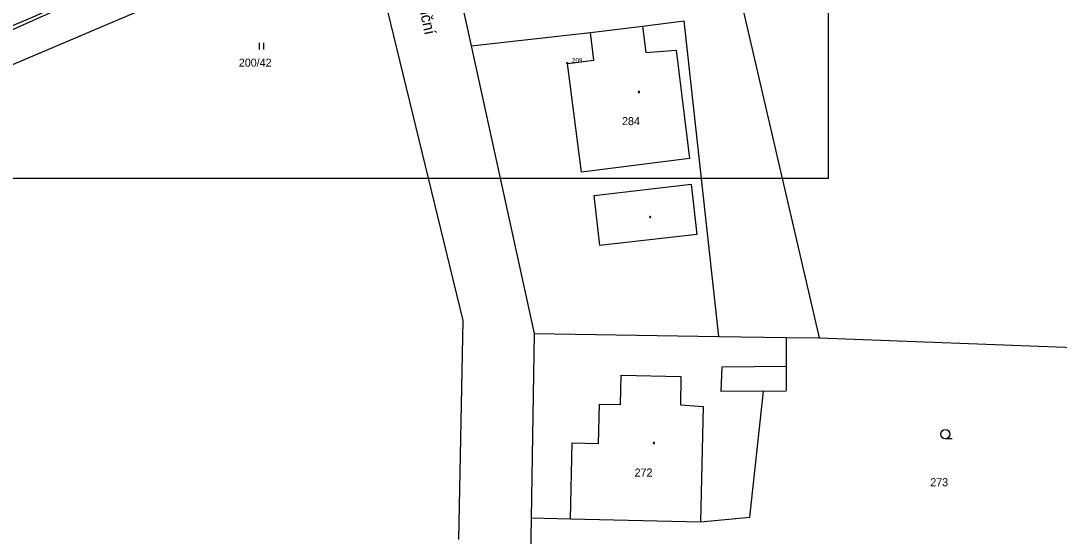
# Model space of a CAD drawing. Extents: x -454285 to -453563, y -1108687 to -1108249.
# Drawn here: x -454018.7 to -453927.9, y -1108561.2 to -1108516.1 of the extents above; entities that cross this region are included whole.
import ezdxf

# ---------------------------------------------------------------- set-up
doc = ezdxf.new("R2010")
doc.units = 0
for name, color, linetype in [('1', 7, 'Continuous'), ('14', 7, 'Continuous'), ('15', 7, 'Continuous'), ('16', 7, 'Continuous'), ('2', 7, 'Continuous'), ('23', 7, 'Continuous'), ('25', 7, 'Continuous'), ('38', 7, 'Continuous'), ('BODY_T1_2018', 7, 'Continuous'), ('CISLA_T1_2018', 7, 'Continuous'), ('okraj asf.komunikace', 7, 'Continuous'), ('rámy', 7, 'Continuous')]:
    doc.layers.add(name, color=color, linetype=linetype)

# ---------------------------------------------------------------- blocks, each defined once
blk = doc.blocks.new('Z402')
for start, end in [(0, 180), (180, 0)]:
    blk.add_arc((0, 0), 0.15, start, end)
blk = doc.blocks.new('Z3040')
blk.add_line((1.5, 0), (0, 0))
blk.add_circle((0, 1), 1)
blk = doc.blocks.new('Z3060')
for p, q in [((-0.5, 1.5), (-0.5, 0)), ((0.5, 1.5), (0.5, 0))]:
    blk.add_line(p, q)
blk = doc.blocks.new('POINT_DISPLAY')
for p, q in [((-0.1, 0), (0.1, 0)), ((0, -0.1), (0, 0.1))]:
    blk.add_line(p, q)
blk.add_circle((0, 0), 0.05)
blk = doc.blocks.new('t1_2018')
at = {"layer": 'BODY_T1_2018'}
blk.add_blockref('POINT_DISPLAY', (-453970.87, -1108519.81), dxfattribs=at)
at = {"layer": 'CISLA_T1_2018'}
blk.add_text('209', height=0.4, dxfattribs=at).set_placement((-453970.47, -1108519.75))

msp = doc.modelspace()

# ---------------------------------------------------------------- linework, layer by layer
at = {"layer": '1'}
for p, q in [((-453960.007, -1108495.681), (-453948.847, -1108543.851)), ((-453982.257, -1108504.751), (-453979.297, -1108518.271)), ((-453988.627, -1108506.811), (-454099.187, -1108553.971)), ((-453979.987, -1108542.331), (-453988.627, -1108506.811)), ((-453968.857, -1108517.121), (-453964.297, -1108516.551)), ((-453964.297, -1108516.551), (-453960.657, -1108516.091)), ((-453957.627, -1108543.721), (-453960.657, -1108516.091)), ((-453979.297, -1108518.271), (-453968.857, -1108517.121)), ((-453979.297, -1108518.271), (-453973.777, -1108543.471)), ((-453980.367, -1108561.481), (-453979.987, -1108542.331)), ((-453973.777, -1108543.471), (-453974.037, -1108559.601)), ((-453973.777, -1108543.471), (-453957.627, -1108543.721)), ((-453957.627, -1108543.721), (-453951.727, -1108543.811)), ((-453951.727, -1108543.811), (-453948.847, -1108543.851)), ((-453951.727, -1108543.811), (-453951.727, -1108546.321)), ((-453948.847, -1108543.851), (-453923.957, -1108544.791)), ((-453951.727, -1108546.321), (-453951.727, -1108548.481)), ((-453954.917, -1108559.551), (-453953.717, -1108548.501)), ((-453953.717, -1108548.501), (-453951.727, -1108548.481)), ((-453974.037, -1108559.601), (-453974.097, -1108563.681)), ((-453974.037, -1108559.601), (-453970.607, -1108559.681)), ((-453970.607, -1108559.681), (-453959.227, -1108559.951)), ((-453959.227, -1108559.951), (-453954.917, -1108559.551))]:
    msp.add_line(p, q, dxfattribs=at)
at = {"layer": '2'}
for p, q in [((-453993.337, -1108505.161), (-454060.357, -1108535.251)), ((-453964.297, -1108516.551), (-453963.997, -1108518.871)), ((-453968.557, -1108519.531), (-453968.857, -1108517.121)), ((-453963.997, -1108518.871), (-453961.367, -1108518.671)), ((-453961.367, -1108518.671), (-453960.177, -1108528.151)), ((-453970.847, -1108519.821), (-453968.557, -1108519.531)), ((-453969.647, -1108529.341), (-453970.847, -1108519.821)), ((-453960.177, -1108528.151), (-453969.647, -1108529.341)), ((-453968.537, -1108531.381), (-453960.047, -1108530.401)), ((-453960.047, -1108530.401), (-453959.547, -1108534.781)), ((-453968.037, -1108535.751), (-453968.537, -1108531.381)), ((-453959.547, -1108534.781), (-453968.037, -1108535.751)), ((-453957.417, -1108548.531), (-453957.337, -1108546.371)), ((-453957.337, -1108546.371), (-453951.727, -1108546.321)), ((-453966.227, -1108549.681), (-453966.157, -1108547.101)), ((-453966.157, -1108547.101), (-453960.937, -1108547.231)), ((-453960.937, -1108547.231), (-453960.987, -1108549.711)), ((-453953.717, -1108548.501), (-453957.417, -1108548.531)), ((-453968.137, -1108553.091), (-453968.047, -1108549.641)), ((-453968.047, -1108549.641), (-453966.227, -1108549.681)), ((-453960.987, -1108549.711), (-453958.987, -1108549.851)), ((-453958.987, -1108549.851), (-453959.227, -1108559.951)), ((-453970.607, -1108559.681), (-453970.457, -1108553.031)), ((-453970.457, -1108553.031), (-453968.137, -1108553.091))]:
    msp.add_line(p, q, dxfattribs=at)
at = {"layer": 'okraj asf.komunikace'}
msp.add_lwpolyline([(-454112.32, -1108555.84), (-454100.65, -1108550.87), (-454089.58, -1108546.38), (-454076.91, -1108541.3), (-454064.18, -1108535.73), (-454053.87, -1108531.55), (-454045.79, -1108528.05), (-454030.23, -1108521.06), (-454017.66, -1108515.77), (-454004.84, -1108509.89), (-453993.47, -1108504.93), (-453991.99, -1108504.49), (-453990.15, -1108504.23), (-453988.99, -1108504.84), (-453987.94, -1108505.97), (-453986.82, -1108510.84)], dxfattribs=at)
at = {"layer": 'rámy'}
msp.add_lwpolyline([(-454047.225, -1108469.854), (-453948.057, -1108469.854), (-453948.057, -1108529.906), (-454047.225, -1108529.906)], close=True, dxfattribs=at)

# ---------------------------------------------------------------- block references
msp.add_blockref('t1_2018', (0, 0))
at = {"layer": '23', "xscale": 0.4, "yscale": 0.4000000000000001}
for name, p in [('Z3060', (-453997.633, -1108518.606)), ('Z3040', (-453937.817, -1108552.671))]:
    msp.add_blockref(name, p, dxfattribs=at)
at = {"layer": '25', "xscale": 0.4, "yscale": 0.4000000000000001}
for p in [(-453964.607, -1108522.311), (-453963.627, -1108533.271), (-453963.297, -1108553.051)]:
    msp.add_blockref('Z402', p, dxfattribs=at)

# ---------------------------------------------------------------- texts
at = {"layer": '14'}
msp.add_text('273', height=0.7, dxfattribs=at).set_placement((-453939.13, -1108556.831))
at = {"layer": '15'}
for s, p in [('284', (-453966.09, -1108525.221)), ('272', (-453964.99, -1108555.981))]:
    msp.add_text(s, height=0.7, dxfattribs=at).set_placement(p)
at = {"layer": '16'}
msp.add_text('200/42', height=0.7, dxfattribs=at).set_placement((-453999.605, -1108520.101))
at = {"layer": '38'}
msp.add_text('Luční', height=1, rotation=282.186, dxfattribs=at).set_placement((-453984.017, -1108514.191))

doc.saveas('drawing.dxf')
